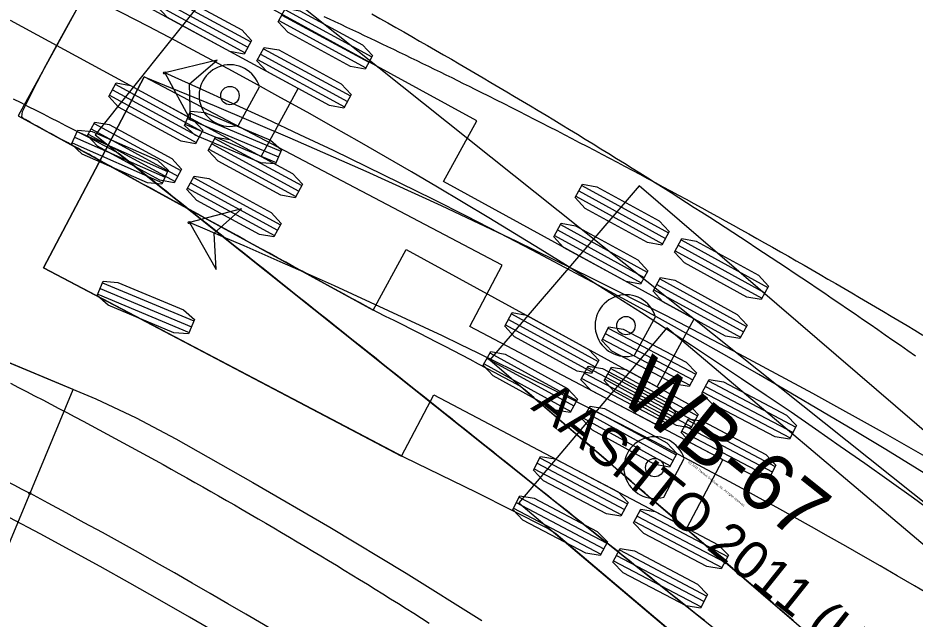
# Model space of a CAD drawing. Extents: x 2175591 to 2194071, y 76570 to 86955.
# Drawn here: x 2192835.16 to 2192868.43, y 86917.59 to 86939.88 of the extents above; entities that cross this region are included whole.
import ezdxf

# ---------------------------------------------------------------- set-up
doc = ezdxf.new("R2010")
doc.units = 0
doc.layers.add('-NOPLT', color=7, linetype='Continuous')
doc.layers.add('C-UTIL-STRM-TEXT', color=7, linetype='Continuous')

msp = doc.modelspace()

# ---------------------------------------------------------------- linework, layer by layer
at = {"layer": '-NOPLT'}
for p, q in [((2192839.018, 86943.274), (2192835.174, 86936.258)), ((2192852.173, 86936.067), (2192839.018, 86943.274)), ((2192845.55, 86937.262), (2192836.238, 86942.326)), ((2192843.326, 86942.199), (2192838.025, 86935.555)), ((2192884.758, 86909.148), (2192843.326, 86942.199)), ((2192840.578, 86940.748), (2192843.8, 86938.997)), ((2192840.359, 86940.346), (2192843.581, 86938.594)), ((2192840.469, 86940.547), (2192843.69, 86938.795)), ((2192844.947, 86939.99), (2192848.168, 86938.239)), ((2192845.056, 86940.192), (2192848.278, 86938.44)), ((2192834.869, 86939.807), (2192844.181, 86934.744)), ((2192844.837, 86939.789), (2192848.059, 86938.037)), ((2192844.268, 86938.742), (2192847.489, 86936.99)), ((2192844.049, 86938.339), (2192847.27, 86936.588)), ((2192844.159, 86938.541), (2192847.38, 86936.789)), ((2192838.771, 86937.425), (2192841.992, 86935.673)), ((2192843.345, 86935.91), (2192844.117, 86937.33)), ((2192844.181, 86934.744), (2192845.55, 86937.262)), ((2192838.552, 86937.022), (2192841.773, 86935.27)), ((2192838.662, 86937.223), (2192841.883, 86935.472)), ((2192835.174, 86936.258), (2192848.329, 86929.051)), ((2192835.174, 86936.258), (2192835.174, 86936.258)), ((2192837.983, 86935.975), (2192841.204, 86934.223)), ((2192850.94, 86933.816), (2192852.173, 86936.067)), ((2192837.353, 86935.671), (2192840.707, 86934.19)), ((2192837.764, 86935.572), (2192840.985, 86933.821)), ((2192837.873, 86935.774), (2192841.095, 86934.022)), ((2192837.168, 86935.252), (2192840.522, 86933.771)), ((2192837.26, 86935.461), (2192840.615, 86933.981)), ((2192838.025, 86935.555), (2192879.458, 86902.504)), ((2192838.025, 86935.555), (2192838.025, 86935.555)), ((2192842.461, 86935.418), (2192845.682, 86933.667)), ((2192842.242, 86935.016), (2192845.463, 86933.264)), ((2192842.351, 86935.217), (2192845.573, 86933.465)), ((2192841.673, 86933.969), (2192844.894, 86932.217)), ((2192841.563, 86933.767), (2192844.784, 86932.016)), ((2192860.236, 86928.722), (2192850.94, 86933.816)), ((2192858.201, 86933.653), (2192852.66, 86927.208)), ((2192856.068, 86933.671), (2192859.283, 86931.909)), ((2192898.388, 86899.098), (2192858.201, 86933.653)), ((2192841.454, 86933.566), (2192844.675, 86931.815)), ((2192855.848, 86933.269), (2192859.063, 86931.507)), ((2192855.958, 86933.47), (2192859.173, 86931.708)), ((2192855.165, 86932.023), (2192858.38, 86930.261)), ((2192855.275, 86932.224), (2192858.491, 86930.462)), ((2192855.055, 86931.822), (2192858.27, 86930.06)), ((2192859.751, 86931.653), (2192862.967, 86929.891)), ((2192848.329, 86929.051), (2192849.562, 86931.302)), ((2192849.562, 86931.302), (2192858.858, 86926.208)), ((2192859.531, 86931.251), (2192862.747, 86929.489)), ((2192859.641, 86931.452), (2192862.857, 86929.69)), ((2192858.848, 86930.005), (2192862.064, 86928.243)), ((2192858.958, 86930.206), (2192862.174, 86928.444)), ((2192858.738, 86929.804), (2192861.954, 86928.042)), ((2192853.347, 86928.705), (2192856.562, 86926.943)), ((2192853.457, 86928.906), (2192856.673, 86927.144)), ((2192858.026, 86927.377), (2192858.802, 86928.795)), ((2192858.858, 86926.208), (2192860.236, 86928.722)), ((2192853.237, 86928.504), (2192856.452, 86926.743)), ((2192852.554, 86927.258), (2192855.77, 86925.496)), ((2192852.664, 86927.459), (2192855.88, 86925.697)), ((2192852.444, 86927.057), (2192855.66, 86925.295)), ((2192852.66, 86927.208), (2192892.847, 86892.653)), ((2192852.66, 86927.208), (2192852.66, 86927.208)), ((2192857.03, 86926.687), (2192860.246, 86924.925)), ((2192857.14, 86926.888), (2192860.356, 86925.126)), ((2192856.92, 86926.486), (2192860.136, 86924.724)), ((2192856.347, 86925.441), (2192859.563, 86923.679)), ((2192856.127, 86925.039), (2192859.343, 86923.277)), ((2192856.237, 86925.24), (2192859.453, 86923.478))]:
    msp.add_line(p, q, dxfattribs=at)
for points in [[(2192840.332, 86940.296), (2192840.605, 86940.798), (2192841.139, 86940.704), (2192843.458, 86939.443), (2192843.827, 86939.047), (2192843.553, 86938.544), (2192843.02, 86938.638), (2192840.701, 86939.899)], [(2192844.81, 86939.739), (2192845.083, 86940.242), (2192845.617, 86940.148), (2192847.936, 86938.887), (2192848.305, 86938.49), (2192848.032, 86937.987), (2192847.498, 86938.081), (2192845.179, 86939.342)], [(2192844.022, 86938.289), (2192844.295, 86938.792), (2192844.829, 86938.698), (2192847.148, 86937.437), (2192847.517, 86937.04), (2192847.243, 86936.538), (2192846.71, 86936.632), (2192844.391, 86937.893)], [(2192840.604, 86937.844), (2192841.561, 86936.088), (2192841.518, 86937.439), (2192842.548, 86938.314)], [(2192838.525, 86936.972), (2192838.798, 86937.475), (2192839.332, 86937.381), (2192841.651, 86936.12), (2192842.019, 86935.723), (2192841.746, 86935.22), (2192841.213, 86935.314), (2192838.894, 86936.575)], [(2192837.737, 86935.522), (2192838.01, 86936.025), (2192838.543, 86935.931), (2192840.863, 86934.67), (2192841.231, 86934.273), (2192840.958, 86933.771), (2192840.425, 86933.865), (2192838.105, 86935.126)], [(2192837.145, 86935.2), (2192837.376, 86935.723), (2192837.915, 86935.673), (2192840.33, 86934.607), (2192840.73, 86934.242), (2192840.499, 86933.719), (2192839.96, 86933.769), (2192837.545, 86934.835)], [(2192842.215, 86934.966), (2192842.488, 86935.468), (2192843.021, 86935.374), (2192845.341, 86934.113), (2192845.709, 86933.717), (2192845.436, 86933.214), (2192844.903, 86933.308), (2192842.583, 86934.569)], [(2192841.427, 86933.516), (2192841.7, 86934.019), (2192842.233, 86933.925), (2192844.552, 86932.664), (2192844.921, 86932.267), (2192844.648, 86931.765), (2192844.115, 86931.858), (2192841.795, 86933.12)], [(2192855.82, 86933.22), (2192856.095, 86933.721), (2192856.628, 86933.626), (2192858.943, 86932.357), (2192859.311, 86931.959), (2192859.036, 86931.458), (2192858.503, 86931.553), (2192856.188, 86932.822)], [(2192855.027, 86931.772), (2192855.302, 86932.274), (2192855.835, 86932.179), (2192858.15, 86930.91), (2192858.518, 86930.512), (2192858.243, 86930.011), (2192857.71, 86930.106), (2192855.395, 86931.375)], [(2192859.504, 86931.201), (2192859.778, 86931.703), (2192860.311, 86931.607), (2192862.627, 86930.339), (2192862.994, 86929.941), (2192862.719, 86929.439), (2192862.186, 86929.535), (2192859.871, 86930.804)], [(2192858.711, 86929.754), (2192858.986, 86930.256), (2192859.519, 86930.16), (2192861.834, 86928.892), (2192862.201, 86928.494), (2192861.926, 86927.992), (2192861.393, 86928.088), (2192859.078, 86929.357)], [(2192853.209, 86928.455), (2192853.484, 86928.956), (2192854.017, 86928.861), (2192856.333, 86927.592), (2192856.7, 86927.194), (2192856.425, 86926.693), (2192855.892, 86926.788), (2192853.577, 86928.057)], [(2192852.417, 86927.008), (2192852.691, 86927.509), (2192853.224, 86927.414), (2192855.54, 86926.145), (2192855.907, 86925.747), (2192855.632, 86925.246), (2192855.099, 86925.341), (2192852.784, 86926.61)], [(2192856.893, 86926.436), (2192857.168, 86926.938), (2192857.701, 86926.843), (2192860.016, 86925.574), (2192860.383, 86925.176), (2192860.108, 86924.675), (2192859.575, 86924.77), (2192857.26, 86926.039)], [(2192856.1, 86924.989), (2192856.375, 86925.491), (2192856.908, 86925.395), (2192859.223, 86924.127), (2192859.59, 86923.729), (2192859.316, 86923.227), (2192858.783, 86923.323), (2192856.467, 86924.592)]]:
    msp.add_lwpolyline(points, close=True, dxfattribs=at)
for points in [[(2192854.553, 86925.579), (2192854.292, 86925.804), (2192854.031, 86926.029), (2192853.763, 86926.244), (2192853.46, 86926.405), (2192853.156, 86926.567), (2192852.852, 86926.728), (2192852.545, 86926.889), (2192852.238, 86927.05), (2192851.93, 86927.212), (2192851.62, 86927.373), (2192851.31, 86927.534), (2192850.998, 86927.695), (2192850.686, 86927.856), (2192850.373, 86928.017), (2192850.058, 86928.177), (2192849.743, 86928.338), (2192849.427, 86928.498), (2192849.11, 86928.658), (2192848.792, 86928.818), (2192848.475, 86928.979), (2192848.16, 86929.144), (2192847.849, 86929.314), (2192847.538, 86929.484), (2192847.227, 86929.654), (2192846.916, 86929.825), (2192846.611, 86929.992), (2192846.306, 86930.159), (2192846.002, 86930.326), (2192845.698, 86930.492), (2192845.394, 86930.659), (2192845.091, 86930.825), (2192844.788, 86930.991), (2192844.487, 86931.156), (2192844.185, 86931.321), (2192843.886, 86931.485), (2192843.586, 86931.649), (2192843.288, 86931.813), (2192842.99, 86931.976), (2192842.694, 86932.138), (2192842.399, 86932.3), (2192842.106, 86932.461), (2192841.813, 86932.621), (2192841.523, 86932.78), (2192841.234, 86932.938), (2192840.948, 86933.095), (2192840.664, 86933.251), (2192840.377, 86933.408), (2192840.086, 86933.567), (2192839.797, 86933.726), (2192839.506, 86933.885), (2192839.217, 86934.043), (2192839.197, 86934.054), (2192839.085, 86934.116), (2192838.968, 86934.18), (2192838.84, 86934.25), (2192838.698, 86934.327), (2192838.594, 86934.384), (2192838.491, 86934.441), (2192838.388, 86934.498), (2192838.287, 86934.553), (2192838.186, 86934.608), (2192838.084, 86934.664), (2192837.986, 86934.718), (2192837.887, 86934.772), (2192837.787, 86934.827), (2192837.691, 86934.879), (2192837.593, 86934.933), (2192837.495, 86934.987), (2192837.401, 86935.038), (2192837.304, 86935.092), (2192837.207, 86935.145), (2192837.113, 86935.196), (2192837.017, 86935.249), (2192836.929, 86935.297), (2192836.844, 86935.344), (2192836.755, 86935.392), (2192836.667, 86935.44), (2192836.583, 86935.487), (2192836.495, 86935.535), (2192836.407, 86935.583), (2192836.322, 86935.629), (2192836.234, 86935.677), (2192836.147, 86935.726), (2192836.063, 86935.772), (2192835.975, 86935.82), (2192835.888, 86935.867), (2192835.804, 86935.913), (2192835.718, 86935.96), (2192835.631, 86936.008), (2192835.548, 86936.054), (2192835.461, 86936.101), (2192835.374, 86936.149), (2192835.305, 86936.218), (2192835.329, 86936.421), (2192835.599, 86936.962), (2192835.871, 86937.5), (2192836.194, 86938.12), (2192836.593, 86938.848), (2192836.985, 86939.564), (2192837.401, 86940.323)], [(2192846.504, 86939.943), (2192846.697, 86939.853), (2192846.914, 86939.751), (2192847.132, 86939.649), (2192847.349, 86939.547), (2192847.567, 86939.444), (2192847.784, 86939.342), (2192848, 86939.239), (2192848.216, 86939.136), (2192848.433, 86939.033), (2192848.649, 86938.93), (2192848.866, 86938.826), (2192849.083, 86938.722), (2192849.299, 86938.618), (2192849.515, 86938.514), (2192849.732, 86938.409), (2192849.948, 86938.304), (2192850.164, 86938.199), (2192850.38, 86938.094), (2192850.597, 86937.988), (2192850.813, 86937.882), (2192851.029, 86937.776), (2192851.244, 86937.67), (2192851.46, 86937.563), (2192851.676, 86937.457), (2192851.892, 86937.35), (2192852.107, 86937.242), (2192852.322, 86937.135), (2192852.608, 86936.992), (2192852.892, 86936.85), (2192853.175, 86936.707), (2192853.458, 86936.564), (2192853.739, 86936.422), (2192854.02, 86936.279), (2192854.3, 86936.136), (2192854.58, 86935.992), (2192854.859, 86935.849), (2192855.138, 86935.705), (2192855.417, 86935.561), (2192855.696, 86935.416), (2192855.975, 86935.271), (2192856.255, 86935.125), (2192856.534, 86934.979), (2192856.814, 86934.832), (2192857.094, 86934.684), (2192857.375, 86934.536), (2192857.657, 86934.386), (2192857.939, 86934.236), (2192858.222, 86934.085), (2192858.506, 86933.933), (2192858.79, 86933.78), (2192859.076, 86933.626), (2192859.362, 86933.471), (2192859.649, 86933.316), (2192859.937, 86933.159), (2192860.226, 86933.001), (2192860.515, 86932.843), (2192860.805, 86932.683), (2192861.095, 86932.523), (2192861.386, 86932.362), (2192861.678, 86932.2), (2192861.97, 86932.037), (2192862.262, 86931.874), (2192862.555, 86931.709), (2192862.848, 86931.544), (2192863.142, 86931.379), (2192863.435, 86931.212), (2192863.729, 86931.046), (2192864.022, 86930.878), (2192864.316, 86930.71), (2192864.61, 86930.541), (2192864.904, 86930.372), (2192865.198, 86930.202), (2192865.492, 86930.032), (2192865.785, 86929.861), (2192866.079, 86929.69), (2192866.372, 86929.518), (2192866.666, 86929.346), (2192866.959, 86929.173), (2192867.252, 86928.999), (2192867.545, 86928.826), (2192867.838, 86928.651), (2192868.13, 86928.477), (2192868.423, 86928.301), (2192868.715, 86928.126)], [(2192848.281, 86940.034), (2192848.578, 86939.867), (2192848.874, 86939.7), (2192849.171, 86939.533), (2192849.466, 86939.365), (2192849.762, 86939.197), (2192850.056, 86939.029), (2192850.351, 86938.86), (2192850.645, 86938.691), (2192850.94, 86938.521), (2192851.233, 86938.351), (2192851.527, 86938.181), (2192851.821, 86938.01), (2192852.114, 86937.838), (2192852.407, 86937.667), (2192852.7, 86937.494), (2192852.993, 86937.322), (2192853.285, 86937.148), (2192853.577, 86936.975), (2192853.869, 86936.801), (2192854.161, 86936.626), (2192854.453, 86936.451), (2192854.744, 86936.276), (2192855.036, 86936.1), (2192855.327, 86935.923), (2192855.617, 86935.747), (2192855.908, 86935.569), (2192856.198, 86935.392), (2192856.488, 86935.214), (2192856.778, 86935.035), (2192857.068, 86934.856), (2192857.358, 86934.677), (2192857.647, 86934.497), (2192857.936, 86934.317), (2192858.224, 86934.136), (2192858.513, 86933.955), (2192858.801, 86933.774), (2192859.089, 86933.592), (2192859.377, 86933.409), (2192859.664, 86933.226), (2192859.951, 86933.043), (2192860.238, 86932.86), (2192860.525, 86932.676), (2192860.811, 86932.491), (2192861.097, 86932.306), (2192861.383, 86932.121), (2192861.669, 86931.935), (2192861.954, 86931.749), (2192862.239, 86931.563), (2192862.524, 86931.376), (2192862.808, 86931.188), (2192863.093, 86931.001), (2192863.377, 86930.812), (2192863.66, 86930.624), (2192863.944, 86930.435), (2192864.227, 86930.245), (2192864.51, 86930.056), (2192864.793, 86929.865), (2192865.075, 86929.675), (2192865.357, 86929.484), (2192865.639, 86929.292), (2192865.92, 86929.1), (2192866.202, 86928.908), (2192866.483, 86928.715), (2192866.763, 86928.522), (2192867.044, 86928.329), (2192867.324, 86928.135), (2192867.604, 86927.94), (2192867.884, 86927.746), (2192868.163, 86927.551), (2192868.442, 86927.355)], [(2192840.604, 86937.844), (2192841.561, 86936.088), (2192841.518, 86937.439), (2192842.548, 86938.314), (2192840.604, 86937.844)], [(2192860.617, 86917.533), (2192860.363, 86917.735), (2192860.11, 86917.938), (2192859.856, 86918.14), (2192859.602, 86918.343), (2192859.348, 86918.545), (2192859.094, 86918.748), (2192858.84, 86918.951), (2192858.586, 86919.153), (2192858.332, 86919.356), (2192858.078, 86919.559), (2192857.823, 86919.761), (2192857.569, 86919.964), (2192857.315, 86920.167), (2192857.061, 86920.37), (2192856.806, 86920.573), (2192856.552, 86920.776), (2192856.297, 86920.979), (2192856.043, 86921.182), (2192855.788, 86921.385), (2192855.533, 86921.588), (2192855.279, 86921.791), (2192855.024, 86921.994), (2192854.769, 86922.198), (2192854.514, 86922.401), (2192854.259, 86922.604), (2192854.004, 86922.808), (2192853.749, 86923.011), (2192853.494, 86923.215), (2192853.239, 86923.418), (2192852.984, 86923.622), (2192852.729, 86923.826), (2192852.473, 86924.029), (2192852.218, 86924.233), (2192851.962, 86924.437), (2192851.707, 86924.641), (2192851.451, 86924.845), (2192851.195, 86925.049), (2192850.94, 86925.253), (2192850.684, 86925.457), (2192850.428, 86925.661), (2192850.171, 86925.865), (2192849.915, 86926.07), (2192849.659, 86926.274), (2192849.403, 86926.479), (2192849.146, 86926.683), (2192848.889, 86926.888), (2192848.633, 86927.093), (2192848.376, 86927.298), (2192848.119, 86927.503), (2192847.862, 86927.708), (2192847.605, 86927.913), (2192847.347, 86928.118), (2192847.09, 86928.324), (2192846.832, 86928.529), (2192846.575, 86928.735), (2192846.317, 86928.94), (2192846.059, 86929.146), (2192845.801, 86929.352), (2192845.543, 86929.558), (2192845.285, 86929.764), (2192845.026, 86929.97), (2192844.768, 86930.176), (2192844.51, 86930.382), (2192844.251, 86930.588), (2192843.993, 86930.794), (2192843.735, 86931), (2192843.476, 86931.206), (2192843.218, 86931.412), (2192842.961, 86931.618), (2192842.703, 86931.823), (2192842.445, 86932.029), (2192842.188, 86932.234), (2192841.932, 86932.439), (2192841.675, 86932.643), (2192841.419, 86932.847), (2192841.163, 86933.051), (2192840.908, 86933.255), (2192840.653, 86933.458), (2192840.399, 86933.661), (2192840.145, 86933.864), (2192839.892, 86934.066), (2192839.639, 86934.268), (2192839.386, 86934.469), (2192839.134, 86934.67), (2192838.882, 86934.871), (2192838.604, 86935.019), (2192838.325, 86935.166), (2192838.046, 86935.312), (2192837.768, 86935.457), (2192837.491, 86935.601), (2192837.214, 86935.745), (2192836.937, 86935.887), (2192836.661, 86936.03), (2192836.384, 86936.172), (2192836.108, 86936.313), (2192835.832, 86936.454), (2192835.555, 86936.594), (2192835.279, 86936.734), (2192835.002, 86936.873)], [(2192834.879, 86926.336), (2192835.18, 86926.182), (2192835.48, 86926.028), (2192835.78, 86925.873), (2192836.08, 86925.717), (2192836.379, 86925.561), (2192836.678, 86925.404), (2192836.977, 86925.247), (2192837.276, 86925.089), (2192837.574, 86924.93), (2192837.872, 86924.772), (2192838.17, 86924.612), (2192838.467, 86924.452), (2192838.765, 86924.292), (2192839.062, 86924.131), (2192839.358, 86923.969), (2192839.654, 86923.807), (2192839.951, 86923.645), (2192840.246, 86923.481), (2192840.542, 86923.318), (2192840.837, 86923.154), (2192841.132, 86922.989), (2192841.426, 86922.824), (2192841.721, 86922.658), (2192842.015, 86922.492), (2192842.309, 86922.325), (2192842.602, 86922.158), (2192842.895, 86921.99), (2192843.188, 86921.822), (2192843.48, 86921.653), (2192843.773, 86921.483), (2192844.064, 86921.313), (2192844.356, 86921.143), (2192844.647, 86920.972), (2192844.938, 86920.8), (2192845.229, 86920.628), (2192845.52, 86920.456), (2192845.81, 86920.283), (2192846.099, 86920.109), (2192846.389, 86919.935), (2192846.678, 86919.761), (2192846.967, 86919.586), (2192847.255, 86919.41), (2192847.544, 86919.234), (2192847.831, 86919.057), (2192848.119, 86918.88), (2192848.406, 86918.703), (2192848.693, 86918.524), (2192848.98, 86918.346), (2192849.266, 86918.167), (2192849.552, 86917.987), (2192849.838, 86917.807), (2192850.123, 86917.626), (2192850.408, 86917.445)], [(2192863.908, 86917.536), (2192863.659, 86917.75), (2192863.41, 86917.964), (2192863.161, 86918.178), (2192862.912, 86918.392), (2192862.663, 86918.606), (2192862.414, 86918.82), (2192862.165, 86919.035), (2192861.915, 86919.249), (2192861.666, 86919.464), (2192861.416, 86919.679), (2192861.166, 86919.894), (2192860.915, 86920.109), (2192860.665, 86920.324), (2192860.414, 86920.54), (2192860.164, 86920.756), (2192859.912, 86920.971), (2192859.661, 86921.187), (2192859.41, 86921.404), (2192859.158, 86921.62), (2192858.906, 86921.837), (2192858.653, 86922.054), (2192858.401, 86922.271), (2192858.147, 86922.489), (2192857.894, 86922.707), (2192857.64, 86922.925), (2192857.386, 86923.144), (2192857.131, 86923.363), (2192856.876, 86923.583), (2192856.62, 86923.802), (2192856.364, 86924.023), (2192856.107, 86924.244), (2192855.849, 86924.465), (2192855.591, 86924.687), (2192855.333, 86924.909), (2192855.074, 86925.132), (2192854.814, 86925.356), (2192854.553, 86925.579)]]:
    msp.add_lwpolyline(points, dxfattribs=at)
for centre, radius in [((2192840.604, 86937.844), 0.0417), ((2192843.021, 86937.006), 0.34), ((2192857.705, 86928.474), 0.34)]:
    msp.add_circle(centre, radius, dxfattribs=at)
for centre, radius, start, end in [((2192733.134, 86734.566), 231.18, 31.07167, 66.3451), ((2192748.446, 86757.375), 185.351, 28.75355, 79.22293), ((2192843.021, 86937.006), 1.143, 16.4652, 286.4652), ((2192746.129, 86724.49), 233.336, 23.25976, 66.11585), ((2192857.705, 86928.474), 1.143, 16.2811, 286.2811)]:
    msp.add_arc(centre, radius, start, end, dxfattribs=at)
at = {"layer": 'C-UTIL-STRM-TEXT'}
for p, q in [((2192839.841, 86937.699), (2192836.114, 86930.62)), ((2192853.113, 86930.71), (2192839.841, 86937.699)), ((2192841.533, 86936.371), (2192844.91, 86934.943)), ((2192841.354, 86935.949), (2192844.731, 86934.521)), ((2192841.443, 86936.16), (2192844.82, 86934.732)), ((2192837.213, 86926.108), (2192823.367, 86931.877)), ((2192836.114, 86930.62), (2192849.386, 86923.631)), ((2192836.114, 86930.62), (2192836.114, 86930.62)), ((2192851.918, 86928.439), (2192853.113, 86930.71)), ((2192838.301, 86930.066), (2192841.681, 86928.646)), ((2192838.124, 86929.644), (2192841.504, 86928.223)), ((2192838.212, 86929.855), (2192841.593, 86928.435)), ((2192861.297, 86923.5), (2192851.918, 86928.439)), ((2192859.224, 86928.392), (2192853.736, 86921.902)), ((2192857.047, 86928.379), (2192860.292, 86926.671)), ((2192899.695, 86894.172), (2192859.224, 86928.392)), ((2192856.834, 86927.974), (2192860.078, 86926.265)), ((2192856.941, 86928.176), (2192860.185, 86926.468)), ((2192856.279, 86926.919), (2192859.523, 86925.211)), ((2192856.172, 86926.716), (2192859.416, 86925.008)), ((2192856.065, 86926.514), (2192859.309, 86924.805)), ((2192860.764, 86926.422), (2192864.008, 86924.714)), ((2192834.136, 86918.723), (2192837.213, 86926.108)), ((2192837.213, 86926.108), (2192837.213, 86926.108)), ((2192860.55, 86926.017), (2192863.794, 86924.308)), ((2192860.657, 86926.219), (2192863.901, 86924.511)), ((2192849.386, 86923.631), (2192850.582, 86925.902)), ((2192850.582, 86925.902), (2192859.961, 86920.963)), ((2192859.995, 86924.962), (2192863.239, 86923.254)), ((2192859.888, 86924.76), (2192863.132, 86923.051)), ((2192859.781, 86924.557), (2192863.026, 86922.848)), ((2192854.409, 86923.369), (2192857.653, 86921.66)), ((2192854.516, 86923.572), (2192857.76, 86921.863)), ((2192859.109, 86922.118), (2192859.862, 86923.549)), ((2192859.961, 86920.963), (2192861.297, 86923.5)), ((2192854.302, 86923.166), (2192857.547, 86921.458)), ((2192853.747, 86922.112), (2192856.991, 86920.403)), ((2192853.534, 86921.706), (2192856.778, 86919.998)), ((2192853.64, 86921.909), (2192856.885, 86920.201)), ((2192853.736, 86921.902), (2192894.207, 86887.681)), ((2192853.736, 86921.902), (2192853.736, 86921.902)), ((2192858.232, 86921.615), (2192861.476, 86919.906)), ((2192858.125, 86921.412), (2192861.37, 86919.704)), ((2192858.019, 86921.209), (2192861.263, 86919.501)), ((2192857.357, 86919.952), (2192860.601, 86918.244)), ((2192857.463, 86920.155), (2192860.708, 86918.446)), ((2192857.25, 86919.749), (2192860.494, 86918.041))]:
    msp.add_line(p, q, dxfattribs=at)
for points in [[(2192892.129, 86889.43), (2192855.115, 86920.736), (2192854.808, 86920.947), (2192852.159, 86922.281), (2192849.493, 86923.58), (2192836.114, 86930.62), (2192839.841, 86937.699), (2192842.44, 86936.632), (2192845.248, 86935.438), (2192848.055, 86934.201), (2192850.854, 86932.924), (2192853.643, 86931.606), (2192856.415, 86930.252), (2192859.169, 86928.861), (2192861.905, 86927.433), (2192864.622, 86925.97), (2192867.319, 86924.471), (2192869.996, 86922.936), (2192872.653, 86921.366), (2192875.289, 86919.761), (2192877.902, 86918.123), (2192880.493, 86916.45)], [(2192834.093, 86927.408), (2192838.046, 86925.753), (2192839.547, 86925.049), (2192841.01, 86924.277), (2192843.872, 86922.662), (2192846.727, 86920.998), (2192849.559, 86919.292), (2192852.366, 86917.544)], [(2192831.983, 86923.954), (2192832.29, 86923.826), (2192832.597, 86923.695), (2192832.903, 86923.562), (2192833.207, 86923.427), (2192833.511, 86923.289), (2192833.813, 86923.149), (2192834.115, 86923.007), (2192834.415, 86922.862), (2192834.714, 86922.714), (2192835.011, 86922.564), (2192835.307, 86922.411), (2192835.602, 86922.255)]]:
    msp.add_lwpolyline(points, dxfattribs=at)
for points in [[(2192841.332, 86935.897), (2192841.555, 86936.424), (2192842.095, 86936.382), (2192844.526, 86935.354), (2192844.932, 86934.995), (2192844.709, 86934.468), (2192844.169, 86934.51), (2192841.738, 86935.538)], [(2192841.517, 86932.296), (2192842.506, 86930.557), (2192842.438, 86931.907), (2192843.452, 86932.801)], [(2192838.102, 86929.592), (2192838.323, 86930.119), (2192838.863, 86930.079), (2192841.297, 86929.056), (2192841.704, 86928.698), (2192841.482, 86928.171), (2192840.942, 86928.211), (2192838.508, 86929.234)], [(2192856.807, 86927.923), (2192857.074, 86928.429), (2192857.608, 86928.343), (2192859.944, 86927.113), (2192860.318, 86926.721), (2192860.052, 86926.215), (2192859.517, 86926.302), (2192857.181, 86927.532)], [(2192856.039, 86926.463), (2192856.305, 86926.97), (2192856.84, 86926.883), (2192859.176, 86925.653), (2192859.549, 86925.261), (2192859.283, 86924.755), (2192858.748, 86924.842), (2192856.413, 86926.072)], [(2192860.524, 86925.966), (2192860.79, 86926.473), (2192861.325, 86926.386), (2192863.661, 86925.156), (2192864.034, 86924.764), (2192863.768, 86924.258), (2192863.233, 86924.345), (2192860.898, 86925.575)], [(2192859.755, 86924.506), (2192860.021, 86925.013), (2192860.556, 86924.926), (2192862.892, 86923.696), (2192863.266, 86923.304), (2192862.999, 86922.798), (2192862.465, 86922.885), (2192860.129, 86924.115)], [(2192854.276, 86923.116), (2192854.542, 86923.622), (2192855.077, 86923.535), (2192857.413, 86922.305), (2192857.787, 86921.914), (2192857.52, 86921.407), (2192856.986, 86921.494), (2192854.65, 86922.724)], [(2192853.507, 86921.656), (2192853.774, 86922.162), (2192854.308, 86922.075), (2192856.644, 86920.845), (2192857.018, 86920.454), (2192856.751, 86919.947), (2192856.217, 86920.034), (2192853.881, 86921.264)], [(2192857.992, 86921.159), (2192858.259, 86921.665), (2192858.793, 86921.578), (2192861.129, 86920.348), (2192861.503, 86919.957), (2192861.236, 86919.45), (2192860.702, 86919.537), (2192858.366, 86920.767)], [(2192857.223, 86919.699), (2192857.49, 86920.205), (2192858.024, 86920.118), (2192860.36, 86918.888), (2192860.734, 86918.497), (2192860.468, 86917.991), (2192859.933, 86918.077), (2192857.597, 86919.307)]]:
    msp.add_lwpolyline(points, close=True, dxfattribs=at)
for centre, radius in [((2192841.517, 86932.296), 0.0417), ((2192858.771, 86923.21), 0.34), ((2192835.602, 86922.255), 0.0417), ((2192835.602, 86922.255), 0.0417)]:
    msp.add_circle(centre, radius, dxfattribs=at)
for centre, radius, start, end in [((2192752.314, 86720.717), 229.614, 55.41684, 67.13934), ((2192858.771, 86923.21), 1.143, 17.2295, 287.2295), ((2192729.537, 86723.348), 225.419, 49.50064, 61.93177)]:
    msp.add_arc(centre, radius, start, end, dxfattribs=at)

# ---------------------------------------------------------------- texts
at = {"layer": '-NOPLT'}
for s, height, p in [('WB-67', 2.125, (2192857.345, 86925.797)), ('AASHTO 2011 (US)', 1.41667, (2192854.149, 86925.402)), ('(c) 2022 Transoft Solutions, Inc. All rights reserved.', 0.085, (2192860.005, 86923.404))]:
    msp.add_text(s, height=height, rotation=321.4203, dxfattribs=at).set_placement(p)

doc.saveas('drawing.dxf')
